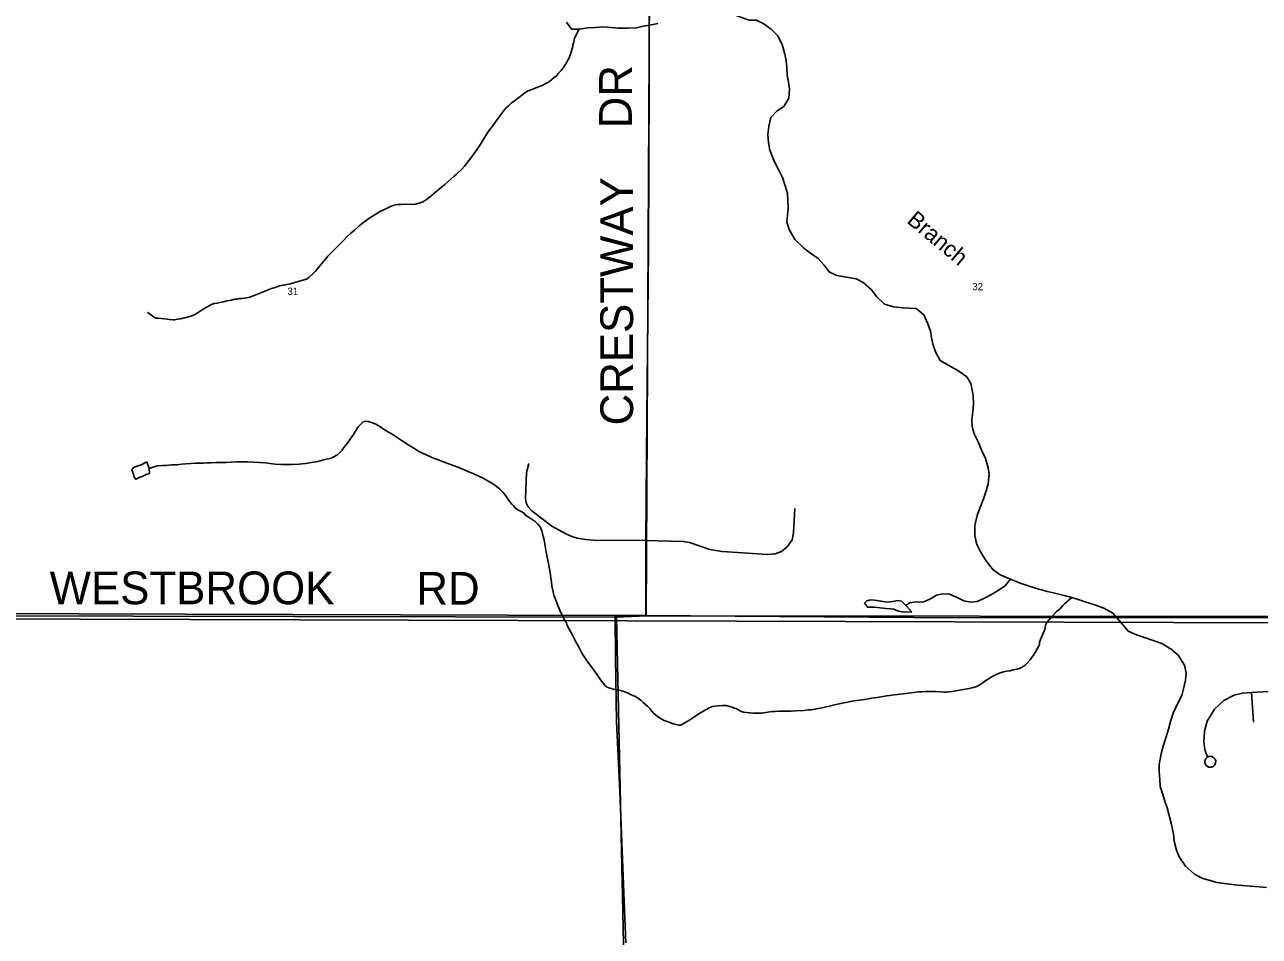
# Model space of a CAD drawing. Extents: x 1312308 to 1684953, y 460642 to 865172.
# Drawn here: x 1444582 to 1454002, y 670241 to 677199 of the extents above; entities that cross this region are included whole.
import ezdxf

# ---------------------------------------------------------------- set-up
doc = ezdxf.new("R2010")
doc.units = 0
for name, color, linetype in [('GM_X_City_Street', 7, 'Continuous'), ('GM_X_City_Street_Text', 7, 'Continuous'), ('GM_X_Corporation', 7, 'Continuous'), ('GM_X_Minor_Lake', 7, 'Continuous'), ('GM_X_Minor_River', 7, 'Continuous'), ('GM_X_Minor_River_Text', 7, 'Continuous'), ('GM_X_Section', 7, 'Continuous'), ('GM_X_Section_Text', 7, 'Continuous')]:
    doc.layers.add(name, color=color, linetype=linetype)

msp = doc.modelspace()

# ---------------------------------------------------------------- linework, layer by layer
at = {"layer": 'GM_X_City_Street'}
for points in [[(1449320.9, 672690.2), (1449320.5, 673262.8), (1449329, 674208.8), (1449341.4, 675485.4), (1449347.1, 676761.2), (1449346.6, 677873.3), (1449346.7, 677942.1), (1449337.6, 677957.3), (1449319.7, 677963.7), (1449298.5, 677977.4), (1449294, 678156.9), (1449298, 678194.6), (1449305, 678255), (1449311.7, 678311.8), (1449319.6, 678382.3), (1449330.9, 678497), (1449345.7, 678801.9), (1449341.7, 678979.2), (1449336.7, 679599.5), (1449331.2, 680430.6), (1449328.6, 680598.2), (1449330.8, 680695.2)], [(1448429.3, 673848.8), (1448409.8, 673780.3), (1448404.6, 673582.8), (1448408.8, 673550.7), (1448423.7, 673518.5), (1448451.2, 673489.2), (1448603.2, 673371.3), (1448710.7, 673314), (1448757.3, 673292.1), (1448798.7, 673279.5), (1448860.3, 673269.3), (1448919.9, 673264.6), (1449320.5, 673262.8)], [(1449320.5, 673262.8), (1449607.6, 673255.5), (1449654.6, 673247.4), (1449810.4, 673193.8), (1449900.5, 673179.2), (1450062, 673168.7), (1450246.1, 673155.7), (1450308.6, 673161.4), (1450357.3, 673179.2), (1450399.5, 673213.3), (1450436.8, 673268.5), (1450448.2, 673320.4), (1450457.9, 673507)], [(1444171.3, 672705.1), (1449086.5, 672689.4), (1449320.9, 672690.2), (1451706.5, 672673), (1453014.7, 672675.7), (1454404.6, 672672.9)], [(1449168, 670191.4), (1449147, 670763.8), (1449122.2, 671346.2), (1449098.5, 671880.4), (1449089.9, 672368.1), (1449086.5, 672689.4)], [(1453608.1, 671609.7), (1453595.6, 671597), (1453587.8, 671579.9), (1453587.2, 671567.5), (1453593.2, 671548.8), (1453613.5, 671532.6), (1453634.9, 671532.7), (1453650, 671538), (1453662.6, 671549.5), (1453669, 671563.7), (1453669.6, 671580.7), (1453665.1, 671593.3), (1453654.1, 671607), (1453639.1, 671614.6), (1453623, 671615.1), (1453608.1, 671609.7), (1453586.5, 671666.5), (1453578.2, 671724.3), (1453583.2, 671806.8), (1453604.5, 671883.1), (1453659.5, 671976.2), (1453731.2, 672041.2), (1453811, 672081.8), (1453874.6, 672098), (1453943.5, 672102), (1454170.8, 672114.2)], [(1453957.1, 671876.1), (1453943.5, 672102)]]:
    msp.add_lwpolyline(points, dxfattribs=at)
at = {"layer": 'GM_X_Corporation'}
for points in [[(1475856.8, 672568.7), (1444174.8, 672664), (1444174.8, 673775.3), (1444174.8, 674127.5), (1444174.7, 674750.1), (1444174.4, 680999.8), (1444007.7, 681035.5), (1444023.9, 682884.1), (1443976.5, 683288.7), (1443962.3, 683833.1), (1443758.9, 683960.3), (1443761, 684493.9), (1443998.9, 684351.1), (1444063.4, 684654.8), (1444174.2, 684716.2), (1444172.9, 704885.4), (1458948.6, 704881.7)], [(1470357.1, 641048.9), (1443692.6, 641278.6), (1443717.6, 642811.7), (1443736.3, 643927.4), (1443816.9, 652104.2), (1443987.8, 662312.5), (1444085.7, 667768), (1444130.8, 670246.6), (1444144.6, 671004.1), (1444174.8, 672664), (1475856.8, 672568.7)]]:
    msp.add_lwpolyline(points, dxfattribs=at)
at = {"layer": 'GM_X_Minor_Lake'}
for points in [[(1445513.6, 673862.3), (1445471.2, 673838.9), (1445433, 673827.5), (1445412.8, 673819.8), (1445398.4, 673798), (1445412, 673767.6), (1445417.6, 673745.5), (1445429.3, 673729.2), (1445455.6, 673742.8)], [(1445455.6, 673742.8), (1445477.8, 673750.5), (1445508.1, 673766), (1445534.2, 673773.6), (1445532.8, 673811.8), (1445513.6, 673862.3)], [(1451273.3, 672798.7), (1451241.3, 672803.2), (1451207.2, 672797.8), (1451165, 672792.5), (1451117.1, 672799.3), (1451065.2, 672808.2), (1451035.1, 672808.7), (1451009, 672801.1), (1450990.7, 672783.4), (1451014.2, 672752.9), (1451066.3, 672754), (1451108.3, 672749.3), (1451156.2, 672744.5), (1451190.2, 672739.9), (1451210.2, 672737.5)], [(1451305.1, 672765.7), (1451273.3, 672798.7)], [(1451210.2, 672737.5), (1451250, 672722.8), (1451293.9, 672716.1), (1451350.1, 672719.1), (1451305.1, 672765.7)]]:
    msp.add_lwpolyline(points, dxfattribs=at)
at = {"layer": 'GM_X_Minor_River'}
for points in [[(1449790.9, 677333.9), (1449844.1, 677331.5), (1449897.9, 677314.6), (1449949.6, 677289.6), (1450005.4, 677272.7), (1450059.1, 677251.7), (1450110.9, 677234.8), (1450164.9, 677233.9), (1450222.5, 677206.8), (1450277.9, 677165.8), (1450329.2, 677114.8), (1450328.6, 677110.6)], [(1448813.5, 677164.4), (1448776.7, 677096.5), (1448774.4, 677080.5), (1448772.1, 677066.5), (1448765.7, 677044.6), (1448763.4, 677030.5), (1448759.2, 677016.6), (1448754.9, 677000.6), (1448750.5, 676982.6), (1448742.1, 676962.7), (1448735.8, 676946.8), (1448727.5, 676928.8), (1448717.1, 676908.9), (1448706.8, 676893.1), (1448692.4, 676873.3), (1448675.9, 676849.5), (1448655.5, 676829.8), (1448639.1, 676810), (1448622.8, 676796.2), (1448586.2, 676766.8), (1448568, 676755), (1448525.5, 676733.7), (1448509.3, 676728), (1448483.1, 676718.4), (1448466.9, 676710.7), (1448444.7, 676701), (1448424.5, 676693.4), (1448410.3, 676685.6), (1448388, 676671.9), (1448363.6, 676652.3), (1448341.3, 676634.6), (1448318.9, 676617), (1448294.5, 676599.3), (1448276.2, 676583.6), (1448257.8, 676565.9), (1448239.4, 676546.1), (1448218.8, 676516.4), (1448190, 676476.8), (1448159.2, 676435.2), (1448130.5, 676399.5), (1448114, 676373.7), (1448099.6, 676353.9), (1448089.2, 676334), (1448072.7, 676308.2), (1448052, 676274.5), (1448029.4, 676240.8), (1447992.3, 676189.2), (1447955.4, 676141.7), (1447936.9, 676120), (1447916.5, 676096.2), (1447877.7, 676058.8), (1447859.4, 676043.1), (1447837, 676023.4), (1447788.1, 675980.1), (1447763.7, 675962.5), (1447745.3, 675944.7), (1447729, 675931), (1447714.8, 675919.2), (1447698.5, 675905.4), (1447668, 675879.9), (1447647.6, 675864.2), (1447625.3, 675850.5), (1447607.1, 675842.8), (1447564.8, 675829.5), (1447540.7, 675827.9), (1447478.6, 675829.1), (1447452.5, 675827.5), (1447420.4, 675826.1), (1447392.2, 675818.5), (1447362, 675807), (1447327.6, 675789.6), (1447289.1, 675770.2), (1447208, 675719.5), (1447169.5, 675692), (1447132.8, 675660.6), (1447098.2, 675631.1), (1447069.7, 675607.5), (1447045.2, 675583.9), (1447010.4, 675546.3), (1446945.1, 675483.3), (1446916.5, 675453.7), (1446896.1, 675432), (1446877.6, 675410.2), (1446861.3, 675392.4), (1446844.9, 675370.7), (1446824.4, 675346.9), (1446801.8, 675319.2), (1446775.3, 675291.6), (1446752.8, 675271.9), (1446738.6, 675260.1), (1446714.4, 675252.5), (1446686.2, 675243), (1446651.9, 675233.6), (1446609.6, 675222.3), (1446567.4, 675213), (1446527.1, 675205.7), (1446492.9, 675194.3), (1446464.6, 675184.7), (1446428.3, 675169.3), (1446371.8, 675148.2), (1446333.4, 675132.9)], [(1448716.7, 677217.6), (1448755.3, 677166.2), (1448813.5, 677164.4), (1448882, 677174.4), (1448936.3, 677176.8), (1448994.7, 677183), (1449054.7, 677177.2), (1449110.8, 677171.4), (1449185.1, 677173.2), (1449249.4, 677175.2), (1449299.9, 677187.8), (1449352.4, 677196.2), (1449413, 677208.4)], [(1450328.6, 677110.6), (1450361.7, 677048), (1450380.5, 676985.4), (1450393.4, 676926.9), (1450396.3, 676872.6), (1450399.1, 676814.3), (1450410.1, 676759.9), (1450417, 676707.6), (1450411.6, 676639.4), (1450374.2, 676573.8), (1450323.5, 676542.7), (1450276.3, 676491.4), (1450260.9, 676423.4), (1450251.5, 676357.3), (1450256.4, 676301), (1450267.2, 676240.5), (1450301.7, 676157.5), (1450336.4, 676088.6), (1450365.3, 676033.8), (1450388, 675961), (1450403, 675910.5), (1450406, 675860.3), (1450408.7, 675797.9), (1450403.7, 675745.8), (1450398.6, 675695.7), (1450415.5, 675635.1), (1450458.1, 675560), (1450527, 675494.4), (1450578.3, 675455.2), (1450637.6, 675413.9), (1450682.7, 675362.8), (1450719.8, 675311.9), (1450779.4, 675284.6), (1450853.4, 675273.1), (1450927.3, 675259.6), (1450978.9, 675232.5), (1451043.9, 675175), (1451083, 675122), (1451142, 675066.6), (1451211.8, 675045.2), (1451281.8, 675037.8), (1451331.9, 675036.8), (1451384, 675031.8), (1451443.2, 674984.4), (1451473.9, 674915.5), (1451492.8, 674858.9), (1451501.8, 674808.5), (1451514.8, 674754), (1451531.7, 674701.5), (1451568.5, 674636.5), (1451634, 674599), (1451703.3, 674559.5), (1451770.6, 674512), (1451801.6, 674461.2), (1451819.9, 674372.4), (1451822.5, 674304.1), (1451817.4, 674247.9), (1451810.1, 674183.8), (1451811.1, 674133.6), (1451828, 674077), (1451854.9, 674020.2), (1451885.5, 673947.3), (1451912.4, 673888.5), (1451933.1, 673817.8), (1451940.1, 673767.4), (1451932.6, 673695.3), (1451919.5, 673641.3), (1451898.2, 673579.4), (1451870.7, 673509.7), (1451849.5, 673453.8), (1451831.9, 673375.8), (1451832.4, 673301.5), (1451845.2, 673238.9), (1451870.2, 673186.2), (1451914.7, 673109), (1451971.5, 673039.6), (1452024.9, 673000.4), (1452104.4, 672966.7), (1452178, 672937.1), (1452253.7, 672911.5), (1452311.5, 672894.3), (1452383.3, 672872.8), (1452441.2, 672859.6), (1452513, 672842.1), (1452572.8, 672826.9), (1452628.7, 672809.7), (1452688.4, 672790.4), (1452746.2, 672771.2), (1452815.9, 672745.7), (1452885.3, 672708.2), (1452950, 672632.6), (1453002.8, 672569.3), (1453064.4, 672541.9), (1453118.2, 672524.8), (1453191.9, 672499.2), (1453259.6, 672475.8), (1453329, 672434.2), (1453384.2, 672386.9)], [(1446333.4, 675132.9), (1446293, 675117.5), (1446238.8, 675110.5), (1446220.7, 675108.8), (1446204.6, 675105), (1446186.5, 675103.4), (1446160.4, 675097.8), (1446128.2, 675092.3), (1446098, 675084.9), (1446071.9, 675079.3), (1446049.7, 675073.7), (1446027.6, 675070.1), (1446007.4, 675062.4), (1445962.9, 675039.1), (1445936.6, 675023.5), (1445906.1, 675002), (1445879.7, 674986.4), (1445857.5, 674976.7), (1445841.4, 674971), (1445815.2, 674965.4), (1445799.1, 674961.7), (1445770.9, 674954.2), (1445746.8, 674950.6), (1445728.7, 674946.9), (1445712.7, 674947.2), (1445686.7, 674949.7), (1445670.7, 674952), (1445648.7, 674954.4), (1445622.7, 674956.8), (1445598.7, 674959.3), (1445582.6, 674959.5), (1445566.7, 674967.9), (1445552.9, 674980.2), (1445535.1, 674992.5), (1445519.3, 675004.8)], [(1447731.3, 673879.4), (1447701.4, 673889.9), (1447673.6, 673902.5), (1447645.8, 673917), (1447590.1, 673942.1), (1447542.6, 673971.1), (1447514.8, 673987.6), (1447491.1, 674004.1), (1447463.4, 674022.7), (1447431.7, 674043.3), (1447400, 674063.9), (1447372.2, 674080.5), (1447352.4, 674092.9), (1447338.5, 674101.2), (1447312.8, 674117.7), (1447297, 674130), (1447279.1, 674140.4), (1447265.3, 674148.7), (1447243.4, 674159.1), (1447203.5, 674169.8), (1447185.6, 674174.2), (1447165.4, 674168.5), (1447149.1, 674152.8), (1447126.6, 674129.1), (1447108.1, 674101.3), (1447091.5, 674071.5), (1447066.8, 674035.8), (1447044.2, 674006.1), (1447027.7, 673984.3), (1447013.3, 673964.5), (1447001, 673948.6), (1446986.7, 673932.8), (1446970.4, 673919), (1446946.1, 673903.4), (1446925.9, 673893.7), (1446911.7, 673888), (1446885.6, 673882.4), (1446855.4, 673874.9), (1446819.1, 673865.5), (1446770.9, 673858.4), (1446724.6, 673851.2), (1446676.4, 673846), (1446624.3, 673842.9), (1446580.2, 673841.7), (1446538.1, 673842.4), (1446494, 673845.2), (1446418.1, 673854.6), (1446374, 673857.4), (1446281.9, 673863.1), (1446237.8, 673861.8), (1446201.7, 673862.5), (1446157.6, 673859.3), (1446119.5, 673857.9), (1446083.4, 673858.6), (1446043.3, 673857.3), (1446005.2, 673856), (1445973.1, 673854.5), (1445943, 673853), (1445910.9, 673851.6), (1445882.9, 673852.1), (1445848.8, 673850.7), (1445812.6, 673847.4), (1445778.5, 673843.9), (1445746.4, 673840.5), (1445702.3, 673839.3), (1445662.1, 673836), (1445634, 673834.5), (1445591.9, 673831.2), (1445532.8, 673811.8)], [(1449711.5, 671928.3), (1449650.7, 671889.2), (1449602, 671859.9), (1449587.9, 671854.2), (1449573.8, 671852.4), (1449549.8, 671856.9), (1449521.9, 671865.4), (1449492.1, 671878), (1449462.3, 671888.6), (1449438.4, 671901), (1449418.6, 671913.4), (1449396.9, 671929.9), (1449381.1, 671944.2), (1449367.4, 671960.6), (1449351.7, 671978.9), (1449335.9, 671995.3), (1449320.2, 672009.6), (1449302.4, 672026), (1449284.7, 672040.4), (1449264.9, 672056.8), (1449243.2, 672071.2), (1449223.3, 672079.6), (1449205.4, 672088), (1449181.5, 672098.5), (1449153.7, 672109), (1449127.8, 672117.5), (1449101.8, 672122), (1449081.8, 672126.3), (1449065.9, 672130.7), (1449039.9, 672137.2), (1449026, 672143.4), (1449012.2, 672153.7), (1448998.5, 672170), (1448982.8, 672188.4), (1448967.1, 672210.8), (1448955.5, 672229), (1448932, 672261.6), (1448920.3, 672279.9), (1448898.8, 672308.4), (1448887.1, 672324.6), (1448857.8, 672365.3), (1448832.4, 672401.9), (1448805.4, 672458.7), (1448795.7, 672476.9), (1448784, 672493.2), (1448758.9, 672545.8), (1448737.6, 672584.4), (1448722, 672612.8), (1448716.4, 672632.9), (1448695, 672665.4), (1448679.5, 672697.9), (1448666.1, 672730.2), (1448650.7, 672766.6), (1448635.4, 672807.1), (1448620.1, 672845.5), (1448610.7, 672879.8), (1448605.3, 672914), (1448601.9, 672944.2), (1448596.5, 672978.4), (1448591.2, 673016.7), (1448584, 673059), (1448576.7, 673099.3), (1448569.4, 673137.6), (1448562, 673173.8), (1448556.6, 673204), (1448551.2, 673236.3), (1448545.7, 673266.5), (1448538.2, 673294.7), (1448532.6, 673316.9), (1448527, 673337.1), (1448521.3, 673353.3), (1448515.5, 673367.4), (1448497.9, 673387.8), (1448478.2, 673406.2), (1448462.3, 673418.6), (1448424.7, 673443.3), (1448398.9, 673457.8), (1448393.2, 673472), (1448369.3, 673482.5), (1448339.6, 673499.1), (1448323.8, 673511.4), (1448312, 673525.7), (1448298.2, 673540), (1448284.5, 673558.3), (1448268.9, 673580.6), (1448251.3, 673605), (1448229.8, 673631.5), (1448208.1, 673654), (1448180.5, 673676.6), (1448150.8, 673697.2), (1448119.1, 673715.8), (1448085.4, 673734.5), (1448047.6, 673753.2), (1448007.9, 673770), (1447970.1, 673786.8), (1447936.3, 673801.4), (1447900.5, 673818.1), (1447866.7, 673830.8), (1447830.8, 673843.4), (1447763.2, 673868.8), (1447731.3, 673879.4)], [(1452104.4, 672966.7), (1452062.2, 672915.9), (1452011.6, 672882.6), (1451959, 672849.4), (1451906.5, 672822.2), (1451850, 672797), (1451799.8, 672791.8), (1451747.9, 672800.7), (1451692.3, 672829.8), (1451638.6, 672852.8), (1451588.6, 672855.6), (1451538.4, 672844.4), (1451487.8, 672815.2), (1451435.4, 672792), (1451383.3, 672794.8), (1451333.1, 672785.7), (1451305.1, 672765.7)], [(1452572.8, 672826.9), (1452517.1, 672779.4), (1452502.8, 672765.6), (1452482.4, 672741.8), (1452455.9, 672720.2), (1452433.4, 672696.5), (1452412.9, 672672.8), (1452394.5, 672653), (1452382.2, 672637.2), (1452371.8, 672617.3), (1452367.4, 672597.3), (1452365.2, 672583.3), (1452348.4, 672541.4), (1452333.7, 672507.5), (1452325.3, 672485.6), (1452325, 672469.6), (1452318.7, 672453.6), (1452291.8, 672407.9), (1452279.4, 672388), (1452250.6, 672348.4), (1452232.2, 672326.6), (1452215.8, 672310.9), (1452193.5, 672295.2), (1452177.3, 672287.5), (1452151.1, 672279.9), (1452125, 672274.3), (1452100.8, 672268.8), (1452076.7, 672265.2), (1452050.5, 672259.6), (1452024.3, 672252.1), (1452000.1, 672242.5), (1451973.8, 672228.9), (1451949.5, 672215.3), (1451908.9, 672187.9), (1451892.7, 672176.1), (1451864.3, 672158.6), (1451846.1, 672148.8), (1451821.8, 672139.2), (1451789.6, 672131.8), (1451687.1, 672115.6), (1451659, 672110), (1451634.9, 672108.5), (1451614.8, 672104.8), (1451594.7, 672105.2), (1451568.7, 672107.7), (1451532.7, 672110.3), (1451496.6, 672111), (1451458.5, 672109.7), (1451426.4, 672108.2), (1451398.4, 672106.7), (1451366.2, 672103.3), (1451326, 672098), (1451283.9, 672092.7), (1451239.7, 672087.5), (1451159.3, 672076.9), (1451086.9, 672064.2), (1451042.7, 672058.9), (1450990.4, 672047.8), (1450932.2, 672040.8), (1450896, 672035.5), (1450861.8, 672028), (1450831.6, 672022.6), (1450797.4, 672015.2), (1450761.2, 672007.8), (1450731, 672000.3), (1450666.6, 671985.4), (1450636.4, 671979.9), (1450610.2, 671974.3), (1450584.1, 671970.8), (1450560.1, 671969.2), (1450529.9, 671965.8), (1450465.7, 671962.9), (1450431.6, 671959.5), (1450403.5, 671960), (1450371.5, 671958.6), (1450337.4, 671959.2), (1450309.3, 671957.7), (1450289.2, 671956), (1450253.1, 671952.7), (1450204.9, 671945.5), (1450186.8, 671945.8), (1450166.8, 671944.2), (1450142.7, 671944.6), (1450118.7, 671947), (1450088.7, 671949.6), (1450066.7, 671952), (1450044.8, 671960.4), (1450029, 671970.8), (1450011.1, 671979.1), (1449995.1, 671983.4), (1449979.2, 671989.7), (1449959.3, 671996.1), (1449933.3, 672002.6), (1449905.3, 672003.1), (1449875.2, 672001.6), (1449851.1, 671998), (1449829, 671994.4), (1449804.7, 671984.8), (1449782.5, 671973.2), (1449737.9, 671945.9), (1449711.5, 671928.3)], [(1453384.2, 672386.9), (1453430.8, 672309.7), (1453445.6, 672249.1), (1453438.5, 672197), (1453425.1, 672130.9), (1453410.1, 672079), (1453380.8, 672021.3), (1453345.2, 671945.6), (1453325.8, 671879.7), (1453308.6, 671821.8), (1453289.2, 671755.8), (1453269.9, 671693.9), (1453254.7, 671633.9), (1453239, 671551.8), (1453237.9, 671499.6), (1453242.7, 671437.2), (1453245.6, 671384.9), (1453262.6, 671330.3), (1453281.5, 671273.7), (1453300.5, 671221.1), (1453315.4, 671164.5), (1453332, 671095.8), (1453346.6, 671023.2), (1453353.5, 670968.8), (1453370.1, 670898.1), (1453391.2, 670847.5), (1453439.9, 670776.2), (1453508.8, 670714.5), (1453570.3, 670683.1), (1453626.2, 670668), (1453678, 670652.9), (1453738, 670643.6), (1453818, 670634), (1453872.1, 670628.9), (1453936.1, 670623.7), (1454002.2, 670618.3), (1454058.2, 670613.2)]]:
    msp.add_lwpolyline(points, dxfattribs=at)
at = {"layer": 'GM_X_Section'}
for points in [[(1454627.2, 678055.6), (1454637.2, 672685.8), (1454413.1, 672682.3), (1449323.6, 672686.6), (1449351.4, 677945.7)], [(1449351.4, 677945.7), (1449323.6, 672686.6), (1449097.4, 672677.1), (1444175.9, 672688), (1444191.8, 677949.4)], [(1444175.9, 672688), (1449097.4, 672677.1), (1449206.8, 667577.3), (1444097.4, 667787.9)], [(1449323.6, 672686.6), (1454413.1, 672682.3), (1454310.2, 667368.7), (1449206.8, 667577.3), (1449097.4, 672677.1)]]:
    msp.add_lwpolyline(points, close=True, dxfattribs=at)

# ---------------------------------------------------------------- texts
at = {"layer": 'GM_X_City_Street_Text'}
for s, rotation, p in [('DR', 90, (1449214.9, 676407.7)), ('CRESTWAY', 90, (1449224.4, 674140.6)), ('WESTBROOK', 0.00001, (1444772.3, 672775.7)), ('RD', 0.00001, (1447570.8, 672772.4))]:
    msp.add_text(s, height=250, rotation=rotation, dxfattribs=at).set_placement(p)
at = {"layer": 'GM_X_Minor_River_Text'}
msp.add_text('Branch', height=125, rotation=320.00258, dxfattribs=at).set_placement((1451305.9, 675693.3))
at = {"layer": 'GM_X_Section_Text'}
for s, p in [('31', (1446586.9, 675137.4)), ('32', (1451811.9, 675172.6))]:
    msp.add_text(s, height=55.25, rotation=0.00001, dxfattribs=at).set_placement(p)

doc.saveas('drawing.dxf')
